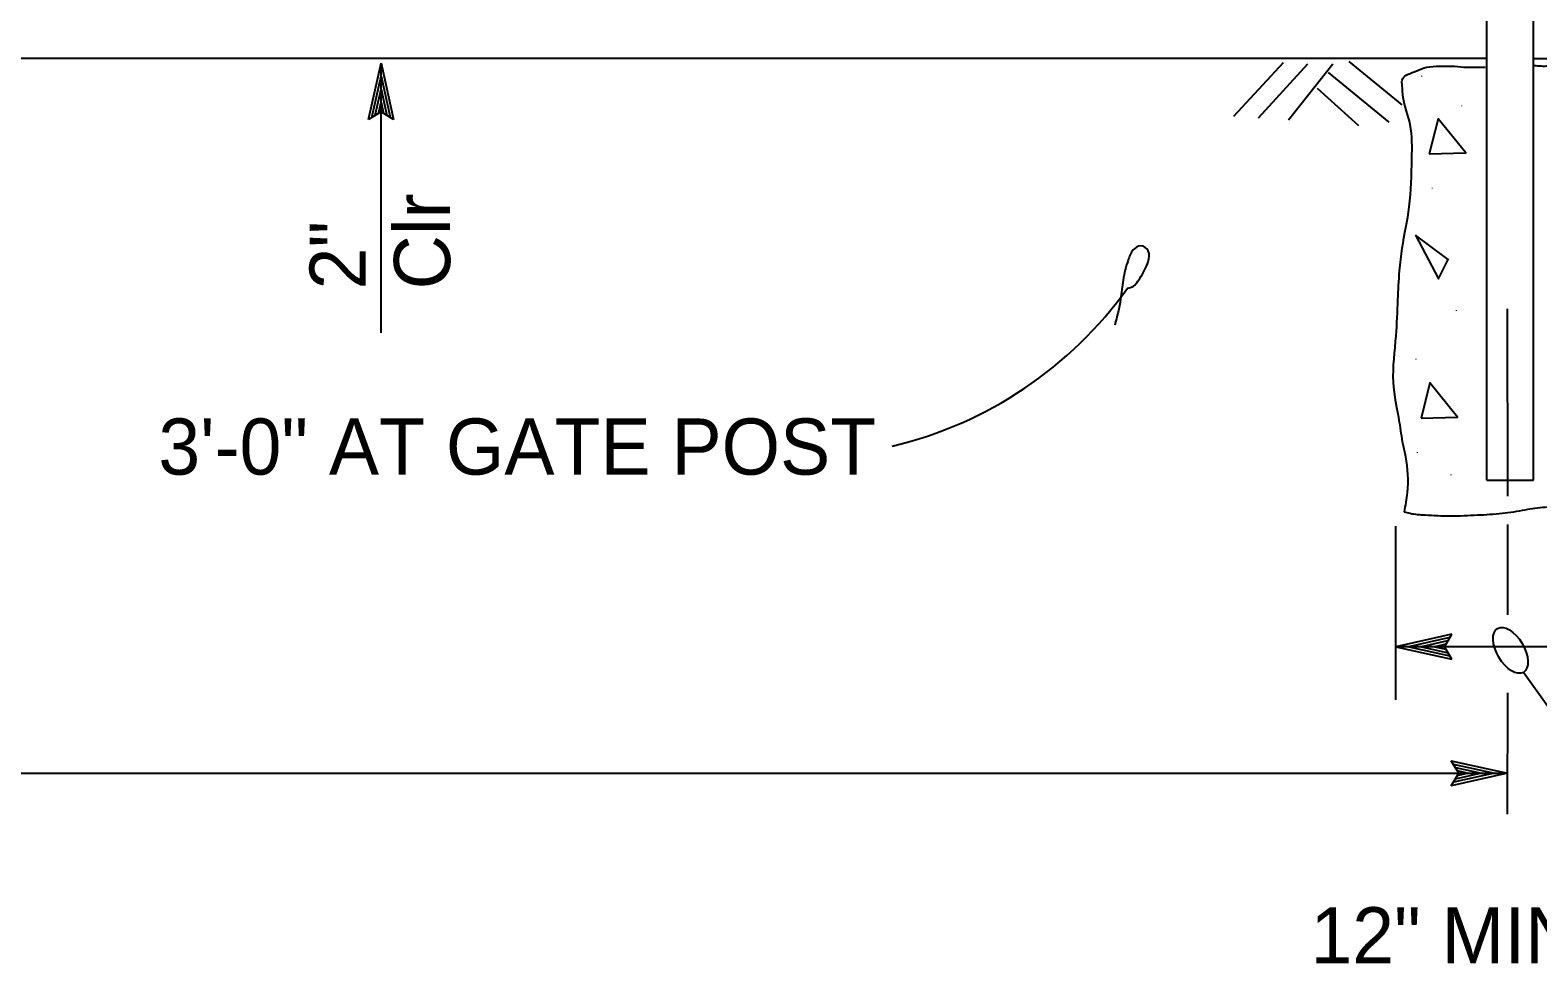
# Model space of a CAD drawing. Extents: x -121875 to -117742, y -103854 to -101122.
# Drawn here: x -120907.1 to -120746.2, y -102479 to -102378.2 of the extents above; entities that cross this region are included whole.
import ezdxf

# ---------------------------------------------------------------- set-up
doc = ezdxf.new("R2010")
doc.units = 0
for name, color, linetype in [('G-MARK', 7, 'Continuous'), ('G-TEXT', 7, 'Continuous'), ('Misc CnstDet(22)', 7, 'Continuous'), ('Nongeo Data(60)', 7, 'Continuous')]:
    doc.layers.add(name, color=color, linetype=linetype)

msp = doc.modelspace()

# ---------------------------------------------------------------- linework, layer by layer
at = {"layer": 'G-MARK'}
for p, q in [((-120869.67, -102410.53), (-120869.67, -102381.74)), ((-120761.41, -102431.16), (-120761.41, -102449.7)), ((-120736.69, -102444.03), (-120761.38, -102444.06)), ((-120727.58, -102475.15), (-120747.75, -102446.78)), ((-121161.89, -102457.55), (-120749.46, -102457.55))]:
    msp.add_line(p, q, dxfattribs=at)
for points in [[(-120749.48, -102407.98), (-120749.46, -102427.98)], [(-120749.46, -102430.98), (-120749.45, -102440.63)], [(-120749.45, -102448.96), (-120749.47, -102461.92)]]:
    msp.add_lwpolyline(points, dxfattribs=at)
msp.add_arc((-120825.05, -102380.7), 43.08, 283.3407, 324.4518, dxfattribs=at)
msp.add_ellipse((-120749.13, -102444.43), major_axis=(-1.38, 2.35), ratio=0.531478, dxfattribs=at)
msp.add_spline([(-120790, -102405.74), (-120789.67, -102405.69), (-120788.69, -102404.71), (-120787.8, -102402.93), (-120787.8, -102401.77), (-120788.6, -102401.24), (-120789.4, -102401.68), (-120789.94, -102402.75), (-120790.47, -102404.89), (-120790.74, -102406.94), (-120791.36, -102409.7)], degree=3, dxfattribs=at)
at = {"layer": 'G-TEXT'}
for p, q in [((-120871.01, -102387.74), (-120869.67, -102381.74)), ((-120869.67, -102381.74), (-120869.67, -102381.74)), ((-120869.67, -102381.74), (-120868.34, -102387.74)), ((-120870.65, -102387.53), (-120869.67, -102383.12)), ((-120869.66, -102383.13), (-120868.7, -102387.51)), ((-120870.29, -102387.29), (-120869.67, -102384.5)), ((-120869.67, -102384.5), (-120869.04, -102387.33)), ((-120869.95, -102387.12), (-120869.67, -102385.89)), ((-120869.67, -102385.89), (-120869.4, -102387.1)), ((-120869.67, -102386.94), (-120871.01, -102387.74)), ((-120871.01, -102387.74), (-120871.01, -102387.74)), ((-120868.34, -102387.74), (-120869.67, -102386.94)), ((-120868.34, -102387.74), (-120868.34, -102387.74)), ((-120755.39, -102442.71), (-120761.38, -102444.06)), ((-120756.19, -102444.05), (-120755.39, -102442.71)), ((-120755.39, -102442.71), (-120755.39, -102442.71)), ((-120761.38, -102444.06), (-120761.38, -102444.06)), ((-120761.38, -102444.06), (-120755.38, -102445.38)), ((-120755.6, -102443.07), (-120760.01, -102444.06)), ((-120759.99, -102444.06), (-120755.62, -102445.02)), ((-120755.84, -102443.43), (-120758.62, -102444.05)), ((-120758.62, -102444.05), (-120755.8, -102444.68)), ((-120756.01, -102443.77), (-120757.24, -102444.05)), ((-120757.24, -102444.05), (-120756.03, -102444.32)), ((-120755.38, -102445.38), (-120756.19, -102444.05)), ((-120755.38, -102445.38), (-120755.38, -102445.38)), ((-120754.66, -102457.55), (-120755.46, -102456.21)), ((-120755.46, -102456.21), (-120755.46, -102456.21)), ((-120755.46, -102456.21), (-120749.46, -102457.55)), ((-120755.24, -102456.57), (-120750.84, -102457.55)), ((-120755.01, -102456.93), (-120752.22, -102457.55)), ((-120754.83, -102457.27), (-120753.61, -102457.55)), ((-120749.46, -102457.55), (-120755.46, -102458.88)), ((-120755.46, -102458.88), (-120754.66, -102457.55)), ((-120755.46, -102458.88), (-120755.46, -102458.88)), ((-120750.85, -102457.55), (-120755.23, -102458.52)), ((-120752.22, -102457.55), (-120755.05, -102458.17)), ((-120753.61, -102457.55), (-120754.81, -102457.81)), ((-120749.46, -102457.55), (-120749.46, -102457.55))]:
    msp.add_line(p, q, dxfattribs=at)
at = {"layer": 'Nongeo Data(60)'}
for p, q in [((-120751.66, -102426.24), (-120751.66, -102366.89)), ((-120746.66, -102426.24), (-120746.66, -102366.89)), ((-120751.66, -102381.24), (-120955.66, -102381.24)), ((-120773.4, -102381.68), (-120778.7, -102387.44)), ((-120770.78, -102381.84), (-120776.07, -102387.6)), ((-120768.11, -102381.84), (-120772.81, -102387.82)), ((-120766.38, -102381.55), (-120760.74, -102386.19)), ((-120746.66, -102381.24), (-120709.24, -102381.24)), ((-120768.58, -102382.74), (-120762.13, -102388.04)), ((-120769.75, -102384.39), (-120765.35, -102388.39)), ((-120751.66, -102426.24), (-120746.66, -102426.24)), ((-120751.66, -102426.24), (-120746.66, -102426.24)), ((-120751.66, -102426.24), (-120746.66, -102426.24))]:
    msp.add_line(p, q, dxfattribs=at)
for points in [[(-120757.81, -102391.43), (-120753.91, -102391.32), (-120756.86, -102387.66)], [(-120759.28, -102400.1), (-120756.81, -102404.75), (-120755.78, -102402.68)], [(-120758.67, -102419.63), (-120754.77, -102419.52), (-120757.73, -102415.86)]]:
    msp.add_lwpolyline(points, close=True, dxfattribs=at)
for points in [[(-120760.68, -102384.14), (-120760.69, -102383.53), (-120760.26, -102383.02), (-120759.4, -102382.67), (-120758.36, -102382.24), (-120757.07, -102382.07), (-120755.09, -102382.07), (-120753.8, -102382.16), (-120752.43, -102382.16), (-120751.83, -102382.16)], [(-120737.85, -102383.88), (-120737.89, -102383.88), (-120737.89, -102383.53), (-120738.07, -102383.1), (-120738.58, -102382.76), (-120739.27, -102382.24), (-120740.04, -102382.07), (-120741.68, -102382.07), (-120742.88, -102381.98), (-120744.26, -102381.98), (-120745.29, -102382.07), (-120746.75, -102381.98)], [(-120760.46, -102429.66), (-120760.12, -102427.58), (-120760.31, -102423.75), (-120760.59, -102422.44), (-120760.97, -102420.1), (-120761.62, -102415.79), (-120761.34, -102410.84), (-120761.15, -102407), (-120760.97, -102403.91), (-120760.69, -102401.48), (-120759.94, -102397.08), (-120759.66, -102391.94), (-120759.84, -102388.29), (-120760.59, -102385.39), (-120760.68, -102384.14)], [(-120737.46, -102429.66), (-120739.07, -102430.01), (-120740.95, -102429.73), (-120745.44, -102429.17), (-120747.59, -102429.45), (-120750.02, -102429.83), (-120752.64, -102430.01), (-120755.54, -102430.11), (-120758.25, -102430.01), (-120759.84, -102429.83), (-120760.46, -102429.66)]]:
    msp.add_spline(points, degree=3, dxfattribs=at)

# ---------------------------------------------------------------- texts
at = {"layer": 'Misc CnstDet(22)'}
for s, p in [('3\'-0" AT GATE POST', (-120893.44, -102425.67)), ('12" MIN,', (-120770.48, -102477.86))]:
    msp.add_text(s, height=6, dxfattribs=at).set_placement(p)
at = {"layer": 'Nongeo Data(60)'}
for s, height, rotation, p in [('.', 0.8, 93.0685, (-120758.55, -102383.26)), ('.', 0.8, 93.0685, (-120754.26, -102386.42)), ('Clr', 6, 90, (-120862.3, -102405.89)), ('.', 0.8, 93.0685, (-120757.42, -102395.22)), ('2"', 6, 90, (-120871.3, -102405.89)), ('.', 0.8, 93.0685, (-120754.84, -102408.29)), ('.', 0.8, 93.0685, (-120759.15, -102413.47)), ('.', 0.8, 93.0685, (-120759, -102423.44)), ('.', 0.8, 93.0685, (-120755.41, -102425.84))]:
    msp.add_text(s, height=height, rotation=rotation, dxfattribs=at).set_placement(p)

doc.saveas('drawing.dxf')
